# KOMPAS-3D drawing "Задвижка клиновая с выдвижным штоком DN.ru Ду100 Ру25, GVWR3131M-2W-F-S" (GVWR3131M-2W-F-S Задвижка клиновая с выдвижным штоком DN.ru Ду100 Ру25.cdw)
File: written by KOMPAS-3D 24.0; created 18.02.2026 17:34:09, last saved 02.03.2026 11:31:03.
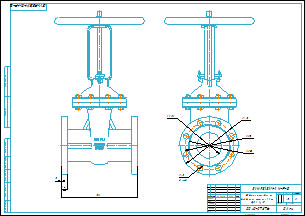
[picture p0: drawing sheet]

Document properties: art: D040-09239; Автор: R2D2; Форматы листов документа: A2; Полное имя файла: GVWR3131M-2W-F-S Задвижка клиновая с выдвижным штоком DN.ru Ду100 Ру25.m3d; Масса: 29; Наименование: Задвижка клиновая с выдвижным штоком DN.ru Ду100 Ру25; Количество листов документа: 1; Примечание: D040-07876

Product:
- Part/product: Задвижка клиновая с выдвижным штоком DN.ru Ду100 Ру25  | designation GVWR3131M-2W-F-S
    Масса: 29
    Раздел спецификации: Прочие изделия
    Примечание: D040-07876

Views: Вид 1, Справа
Referenced files in E:\Работа\Зайцев\GVWR3131M-2W-F-S Задвижка клиновая с выдвижным штоком DN.ru Ду50-200 Ру63\DN100\: GVWR3131M-2W-F-S Задвижка клиновая с выдвижным штоком DN.ru Ду100 Ру63.m3d
Referenced files in E:\Работа\Зайцев\GVWR3131M-2W-F-S Задвижка клиновая 30нж64нж DN.ru  Ду50-150 Ру25\исходные данные\DN100\dn100\: GVWR3131M-2W-F-S Задвижка клиновая с выдвижным штоком DN.ru Ду100 Ру25.m3d
Referenced files in E:\Работа\Зайцев\Для компаса\: чертеж DN.ru А3.cdt
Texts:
  GVWR3131M-2W-F-S
  чертеж DN.ru А3.cdt
  Задвижка клиновая с
  выдвижным штоком DN.ru
  Ду100 Ру25
  Задвижка клиновая с выдвижным штоком DN.ru Ду100 Ру25
  GVWR3131M-2W-F-S Задвижка клиновая с выдвижным штоком DN.ru Ду100 Ру25
Dimensions and other numbers on the sheet: 0; 3; 2; 4; 300; 24; 1:2; 1; 29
